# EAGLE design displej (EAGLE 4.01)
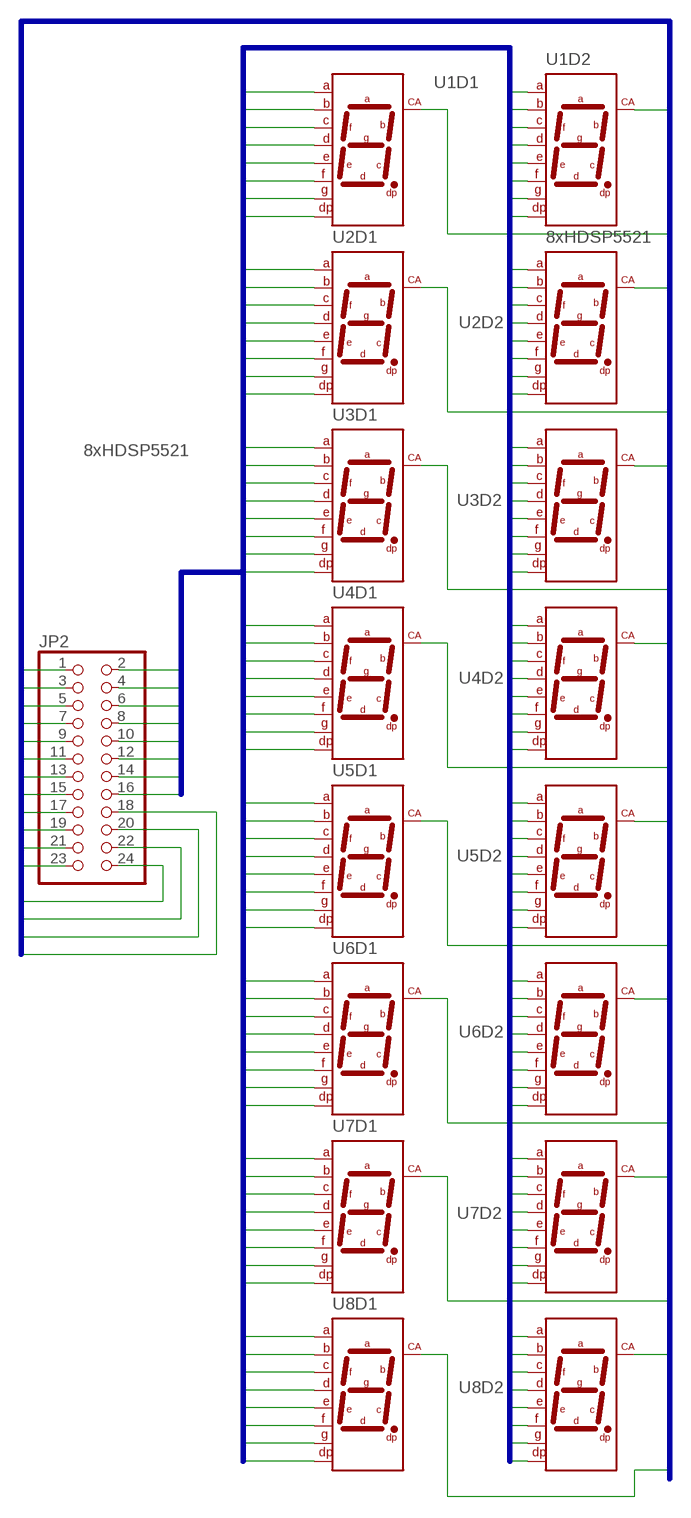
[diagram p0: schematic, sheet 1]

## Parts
JP2  PINHD-2X12  [2X12]
U1  8xHDSP5521  HD-A542D  [7SEGHD18]
U2  HD-A542D  [7SEGHD18]
U3  HD-A542D  [7SEGHD18]
U4  HD-A542D  [7SEGHD18]
U5  HD-A542D  [7SEGHD18]
U6  HD-A542D  [7SEGHD18]
U7  HD-A542D  [7SEGHD18]
U8  HD-A542D  [7SEGHD18]

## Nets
SEGMENT_KATODY_0: JP2.16 U1.11(D2:A) U1.16(D1:A) U2.11(D2:A) U2.16(D1:A) U3.11(D2:A) U3.16(D1:A) U4.11(D2:A) U4.16(D1:A) U5.11(D2:A) U5.16(D1:A) U6.11(D2:A) U6.16(D1:A) U7.11(D2:A) U7.16(D1:A) U8.11(D2:A) U8.16(D1:A)
SEGMENT_KATODY_1: JP2.14 U1.10(D2:B) U1.15(D1:B) U2.10(D2:B) U2.15(D1:B) U3.10(D2:B) U3.15(D1:B) U4.10(D2:B) U4.15(D1:B) U5.10(D2:B) U5.15(D1:B) U6.10(D2:B) U6.15(D1:B) U7.10(D2:B) U7.15(D1:B) U8.10(D2:B) U8.15(D1:B)
SEGMENT_KATODY_2: JP2.12 U1.3(D1:C) U1.8(D2:C) U2.3(D1:C) U2.8(D2:C) U3.3(D1:C) U3.8(D2:C) U4.3(D1:C) U4.8(D2:C) U5.3(D1:C) U5.8(D2:C) U6.3(D1:C) U6.8(D2:C) U7.3(D1:C) U7.8(D2:C) U8.3(D1:C) U8.8(D2:C)
SEGMENT_KATODY_3: JP2.10 U1.2(D1:D) U1.6(D2:D) U2.2(D1:D) U2.6(D2:D) U3.2(D1:D) U3.6(D2:D) U4.2(D1:D) U4.6(D2:D) U5.2(D1:D) U5.6(D2:D) U6.2(D1:D) U6.6(D2:D) U7.2(D1:D) U7.6(D2:D) U8.2(D1:D) U8.6(D2:D)
SEGMENT_KATODY_4: JP2.8 U1.1(D1:E) U1.5(D2:E) U2.1(D1:E) U2.5(D2:E) U3.1(D1:E) U3.5(D2:E) U4.1(D1:E) U4.5(D2:E) U5.1(D1:E) U5.5(D2:E) U6.1(D1:E) U6.5(D2:E) U7.1(D1:E) U7.5(D2:E) U8.1(D1:E) U8.5(D2:E)
SEGMENT_KATODY_5: JP2.6 U1.12(D2:F) U1.18(D1:F) U2.12(D2:F) U2.18(D1:F) U3.12(D2:F) U3.18(D1:F) U4.12(D2:F) U4.18(D1:F) U5.12(D2:F) U5.18(D1:F) U6.12(D2:F) U6.18(D1:F) U7.12(D2:F) U7.18(D1:F) U8.12(D2:F) U8.18(D1:F)
SEGMENT_KATODY_6: JP2.4 U1.7(D2:G) U1.17(D1:G) U2.7(D2:G) U2.17(D1:G) U3.7(D2:G) U3.17(D1:G) U4.7(D2:G) U4.17(D1:G) U5.7(D2:G) U5.17(D1:G) U6.7(D2:G) U6.17(D1:G) U7.7(D2:G) U7.17(D1:G) U8.7(D2:G) U8.17(D1:G)
SEGMENT_KATODY_7: JP2.2 U1.4(D1:DP) U1.9(D2:DP) U2.4(D1:DP) U2.9(D2:DP) U3.4(D1:DP) U3.9(D2:DP) U4.4(D1:DP) U4.9(D2:DP) U5.4(D1:DP) U5.9(D2:DP) U6.4(D1:DP) U6.9(D2:DP) U7.4(D1:DP) U7.9(D2:DP) U8.4(D1:DP) U8.9(D2:DP)
VSTUP_ANODY0: JP2.17 U1.14(D1:CA)
VSTUP_ANODY1: JP2.19 U1.13(D2:CA)
VSTUP_ANODY2: JP2.21 U2.14(D1:CA)
VSTUP_ANODY3: JP2.23 U2.13(D2:CA)
VSTUP_ANODY4: JP2.24 U3.14(D1:CA)
VSTUP_ANODY5: JP2.22 U3.13(D2:CA)
VSTUP_ANODY6: JP2.20 U4.14(D1:CA)
VSTUP_ANODY7: JP2.18 U4.13(D2:CA)
VSTUP_ANODY8: JP2.15 U5.14(D1:CA)
VSTUP_ANODY9: JP2.13 U5.13(D2:CA)
VSTUP_ANODY10: JP2.11 U6.14(D1:CA)
VSTUP_ANODY11: JP2.9 U6.13(D2:CA)
VSTUP_ANODY12: JP2.7 U7.14(D1:CA)
VSTUP_ANODY13: JP2.5 U7.13(D2:CA)
VSTUP_ANODY14: JP2.3 U8.14(D1:CA)
VSTUP_ANODY15: JP2.1 U8.13(D2:CA)

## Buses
SEGMENT_KATODY_[0..7]
VSTUP_ANODY[0..15]

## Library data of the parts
JP2 = pinhead:PINHD-2X12: PIN HEADER
U1-U8 = GM99:HD-A542D

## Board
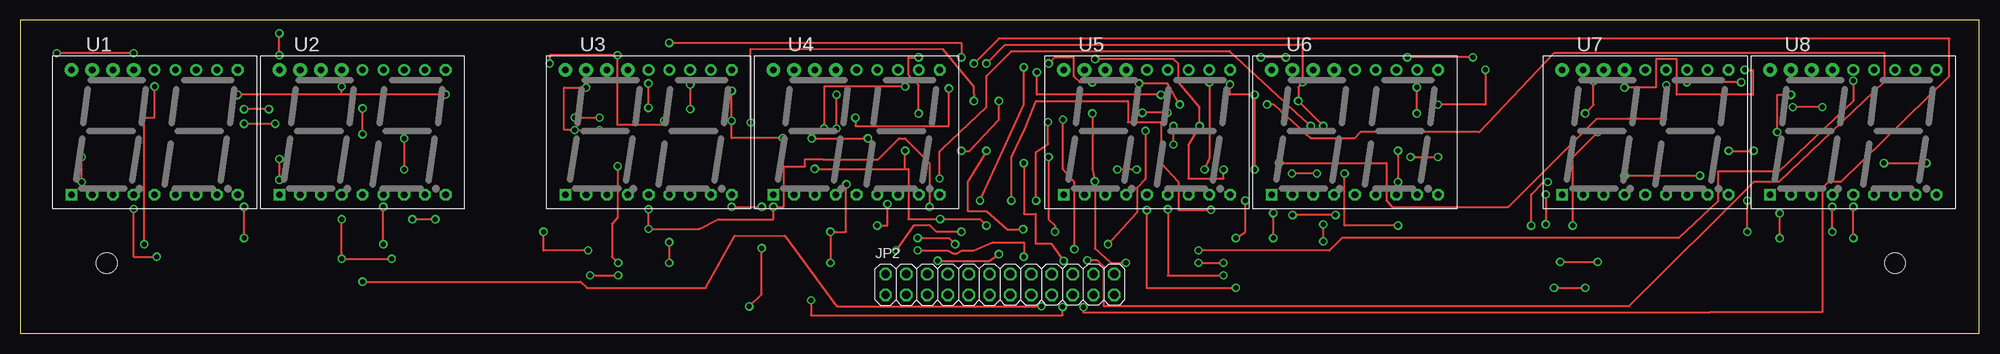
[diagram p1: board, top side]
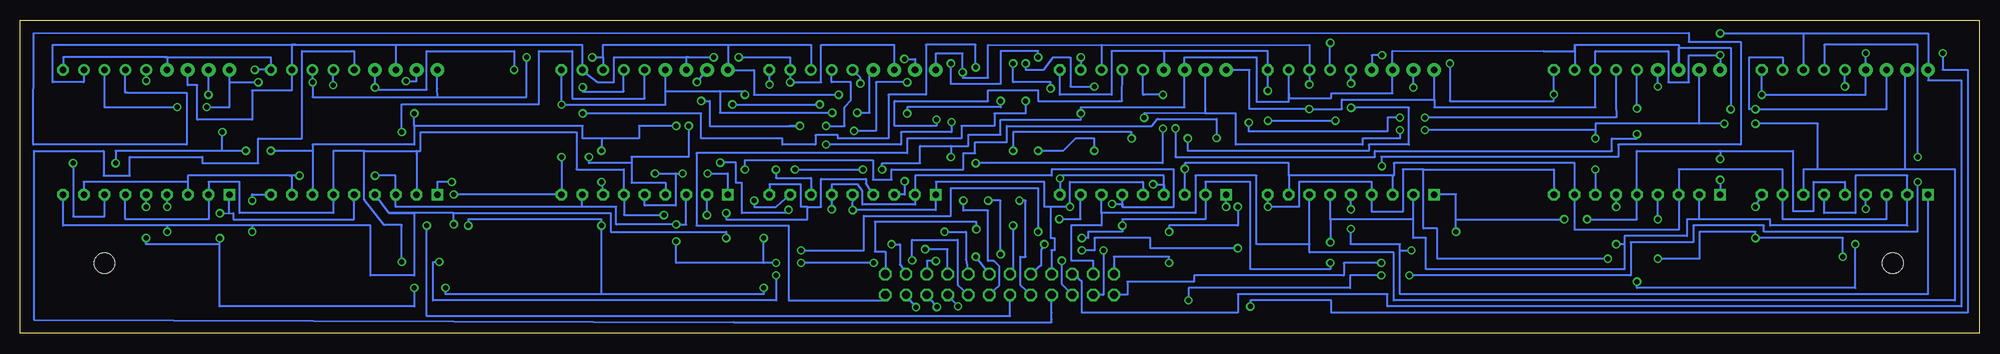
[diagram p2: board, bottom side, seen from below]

Size 239.24 x 38.27 mm. Coordinates in mm from the lower left corner, seen from the top.
Outline: 0,0 239.24,0 239.24,38.27 0,38.27 0,0
Copper layers used: Top, Bottom
Holes 2.54 mm at 10.54,8.61 228.98,8.61

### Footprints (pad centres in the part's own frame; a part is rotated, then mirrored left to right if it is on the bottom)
2X12 = drill 1.016 octagon: 1 -13.97,-1.27; 2 -13.97,1.27; 3 -11.43,-1.27; 4 -11.43,1.27; 5 -8.89,-1.27; 6 -8.89,1.27; 7 -6.35,-1.27; 8 -6.35,1.27; 9 -3.81,-1.27; 10 -3.81,1.27; 11 -1.27,-1.27; 12 -1.27,1.27; 13 1.27,-1.27; 14 1.27,1.27; 15 3.81,-1.27; 16 3.81,1.27; 17 6.35,-1.27; 18 6.35,1.27; 19 8.89,-1.27; 20 8.89,1.27; 21 11.43,-1.27; 22 11.43,1.27; 23 13.97,-1.27; 24 13.97,1.27
7SEGHD18 = drill 0.813 pad 1.422 square: 1 0,0 | drill 0.813 pad 1.422 octagon: 2 2.54,0; 3 5.08,0; 4 7.62,0; 5 10.16,0; 6 12.7,0; 7 15.24,0; 8 17.78,0; 9 20.32,0; 10 20.32,15.24 | drill 0.813 pad 1.422 round: 11 17.78,15.24; 12 15.24,15.24; 13 12.7,15.24; 14 10.16,15.24 | drill 0.813 pad 1.676 round: 15 7.62,15.24; 16 5.08,15.24; 17 2.54,15.24; 18 0,15.24

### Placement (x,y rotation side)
JP2  119.64,5.98 0 top
U1  6.22,16.97 0 top
U2  31.62,16.97 0 top
U3  66.56,16.97 0 top
U4  91.96,16.97 0 top
U5  127.44,16.97 0 top
U6  152.84,16.97 0 top
U7  188.32,16.97 0 top
U8  213.72,16.97 0 top

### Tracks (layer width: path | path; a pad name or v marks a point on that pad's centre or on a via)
SEGMENT_KATODY_0  (via drill 0.61)
  Top 0.254: v154.55,33.76 v151.51,33.76 | v126.36,12.42 126.36,13.19 125.6,13.95 v125.6,21.57 | v144.65,20.04 145.21,21.42 v145.21,30.71 | v136.34,20.04 v133.98,20.04 | v109.72,26.9 109.72,30.33 108.48,31.58 108.48,33.73 109.72,33.73 v109.72,33.76 | v30.35,27.41 30.35,27.43 | v30.35,27.41 | v27.3,27.41 v30.35,27.41
  Bottom 0.254: 145.21,32.24 v145.21,30.71 141.45,30.71 141.45,35.28 132.53,35.28 132.53,34.22 U5.16 | 157.6,33.76 v154.55,33.76 | v151.51,33.76 145.21,33.76 145.21,32.24 | 145.21,32.24 U5.11 | 193.42,35.28 193.42,33 U7.16 | 205.61,35.28 193.42,35.28 | 205.61,35.28 235.33,35.28 235.33,30.71 231.52,30.71 231.52,32.24 U8.11 | 218.79,30.33 217.65,30.33 217.65,26.14 210.94,26.14 210.94,29.7 206.1,29.7 U7.11 206.1,35.28 205.61,35.28 | U1.11 24,33.76 28.06,33.76 28.06,27.41 v27.3,27.41 11.3,27.41 U1.16 | 49.4,35.28 36.7,35.28 U2.16 36.7,34.94 30.35,34.94 v30.35,27.41 | 49.4,35.28 U2.11 | 84.32,29.37 84.32,32.24 U3.11 | 84.32,29.37 84.32,29.36 84.32,28.79 79.12,28.79 79.12,29.36 71.65,29.37 U3.16 71.65,33.02 71.65,34.55 53.21,34.52 49.4,34.52 49.4,35.28 | v126.36,12.42 123.77,12.42 123.77,8.99 JP2.16 | 125.6,22.94 v125.6,21.57 | 125.6,22.94 123.46,22.94 123.46,24.31 119.5,24.31 119.5,26.14 109.72,26.14 v109.72,26.9 109.72,27.66 97.04,27.66 U4.16 97.05,33.77 96.64,33.76 88.26,33.76 88.26,28.32 84.32,28.32 84.32,29.37 | v144.65,20.04 v136.34,20.04 | v133.98,20.04 133.98,20.81 129.33,20.81 129.33,22.94 125.6,22.94 | v109.72,33.76 U4.11 | U6.16 157.92,33.76 157.6,33.76 | 157.6,33.76 166.75,33.76 166.75,30.71 168.73,30.71 U6.11 170.62,35.28 193.42,35.28 | 218.79,30.33 218.8,30.33 | U8.16 218.8,30.33 218.79,30.33 | v30.35,27.41
SEGMENT_KATODY_1  (via drill 0.61)
  Top 0.254: v140.08,26.98 v137.03,26.98 | 211.63,32.21 211.63,29.19 202.31,29.19 202.31,33.51 199.77,33.51 199.77,30.08 v195.93,30.08 | v64.64,33 64.64,34.01 v72.92,34.01 72.92,25.48 78.61,25.48 v78.61,26.01 | v86.89,29.68 v86.87,26 86.86,23.88 v93.14,23.88 | v122.55,9.38 122.55,11.15 118.74,11.15 116.45,10.14 114.93,10.14 114.42,9.81 113.91,9.81 113.28,10.14 v109.6,10.14 | v90.55,10.42 90.55,4.8 v89.02,3.28 | v13.84,34.27 v4.44,34.27 | v150.74,20.04 v150.74,29.19 147.75,29.19 v147.75,30.43 | v178.94,32.24 178.94,27.97 v173.15,27.97 | 39.24,29.21 v26.54,29.19 | v51.94,29.21 39.24,29.21 | 39.24,29.21 v39.24,30.18 | v210.61,32.24 210.61,32.21 211.63,32.21 | 211.63,32.21 211.63,32.24
  Bottom 0.254: 221.61,33.76 208.66,33.76 208.66,32.24 U7.10 208.64,32.24 v210.61,32.24 | v150.74,29.19 150.74,29.64 153.79,29.64 | v137.03,26.98 135.5,26.98 135.5,31.47 U5.15 | v140.08,26.98 153.79,26.98 153.79,29.64 | v178.94,32.24 178.94,34.52 189.61,34.52 189.61,29.82 195.93,29.82 v195.93,30.08 U7.15 | 99.69,34.52 86.88,34.52 86.88,32.24 U3.10 v86.88,29.67 | 99.69,34.52 99.58,34.52 U4.15 | 99.69,34.52 105.96,34.52 105.96,29.19 112.26,29.19 112.26,32.24 U4.10 | 51.94,32.24 U2.10 v51.94,29.21 51.94,28.43 64.64,28.43 v64.64,33 | v72.92,34.01 74.17,34.01 U3.15 | v86.87,26 86.74,26.01 v78.61,26.01 | v109.6,10.14 108.07,10.14 108.07,11.66 101.24,11.66 101.24,10.42 v90.55,10.42 | v89.02,3.28 89.02,4.04 79.12,4.04 79.12,2.52 1.39,2.52 1.39,32.24 4.44,32.24 v4.44,34.27 | 26.54,32.24 U1.10 v26.54,29.19 13.84,29.19 U1.15 v13.84,34.27 | v150.74,20.04 150.74,21.19 135.12,21.19 135.12,18.8 132.84,18.8 132.84,20.04 124.07,20.04 124.07,22.02 122.63,22.02 122.63,23.4 118.74,23.4 118.74,25.38 101.04,25.38 100.32,26.22 93.14,26.22 v93.14,23.88 | v86.88,29.67 v86.89,29.67 v86.89,29.68 | v86.88,29.67 86.86,29.67 | v122.55,9.38 JP2.14 | U5.10 147.76,30.44 v147.75,30.43 | U6.15 160.46,29.64 160.45,29.64 | 160.45,29.64 153.79,29.64 | 160.45,29.64 160.45,27.97 v173.15,27.97 173.15,32.21 U6.10 | U8.10 234.04,33.76 221.61,33.76 | U8.15 221.34,33.76 221.61,33.76 | v39.24,30.18 U2.15
SEGMENT_KATODY_2  (via drill 0.61)
  Top 0.254: v135.02,8.61 133.22,8.61 131.24,10.37 v131.24,18.6 130.93,20.04 v130.93,26.9 | v143.89,8.61 v146.93,8.61 | v159.13,11.26 v159.13,13.31 | v149.6,16.23 149.6,12.42 v148.46,11.66 | v195.93,19.28 v205.15,19.28 | v117.98,13.19 117.22,13.97 v112.34,13.97 108.45,13.97 108.46,20.12 108.07,20.12 | v119.5,28.43 119.5,26.14 115.95,22.33 v114.93,22.33 | 108.07,20.12 v108.07,22.33 | v97.02,20.12 108.07,20.12 | 108.07,20.12 108.05,20.12 | 108.07,20.12
  Bottom 0.254: 206.37,19.28 218.79,19.28 218.79,18.52 | 218.79,18.52 231.52,18.52 231.52,17 U8.8 | v135.02,8.61 v143.89,8.61 | 148.46,8.61 159.13,8.61 v159.13,11.26 | v146.93,8.61 148.46,8.61 | v149.6,16.23 149.6,15.47 146.93,15.47 U5.8 | 148.46,8.61 v148.46,11.66 | 159.18,13.31 166.47,13.31 166.47,15.47 170.58,15.47 | 193.42,17 193.42,15.47 170.58,15.47 | v195.93,19.28 193.42,19.28 193.42,17 | 193.42,17 U7.3 | 24,17 24,13.95 11.3,13.95 U1.3 11.3,17 | 24,17 24,20.04 36.7,20.04 36.7,17 | 24,17 U1.8 | v117.98,13.19 117.98,7.85 JP2.12 | 84.32,19.28 84.32,17 U3.8 | 71.65,19.28 U3.3 | 71.65,19.28 71.5,19.28 71.5,20.81 49.4,20.81 U2.8 49.4,12.68 36.7,12.68 36.7,17 | 71.65,19.28 84.32,19.28 | 84.32,19.28 84.32,20.81 97.02,20.81 v97.02,20.12 97.03,19.58 U4.3 | 36.7,17 U2.3 | v130.93,26.9 130.93,27.66 119.5,27.66 v119.5,28.43 | v114.93,22.33 111.88,22.33 110.36,23.85 108.07,23.85 v108.07,22.33 | U5.3 131.24,16.97 v131.24,18.6 | v159.13,13.31 159.18,13.31 | U6.3 157.92,13.31 159.18,13.31 | U6.8 170.62,15.47 170.58,15.47 | v205.15,19.28 206.37,19.28 | U7.8 206.1,19.28 206.37,19.28 | U8.3 218.8,18.52 218.79,18.52 | U4.8 109.74,13.97 v112.34,13.97
SEGMENT_KATODY_3  (via drill 0.61)
  Top 0.254: v160.65,14.46 v155.39,14.46 | v44.32,10.9 v44.32,15.47 | v114.17,10.9 113.41,11.66 v109.6,11.66 | v79.24,11.15 v79.24,8.61 | v188.08,8.74 v192.65,8.74 | v105.89,15.83 105.89,13.19 v104.64,13.19 | v140.14,15.17 140.14,7.09 v146.93,7.09
  Bottom 0.254: 201.04,17 201.04,14.71 212.47,14.71 212.47,18.52 216.28,18.52 216.28,17 | 201.04,17 U7.6 | 216.28,17 216.28,13.95 226.42,13.95 U8.6 | 216.28,17 U8.2 | v155.39,14.46 155.39,17 U6.2 | v160.65,14.46 160.65,14.51 165.53,14.51 165.53,16.97 U6.6 165.54,20.04 171.32,20.04 171.32,24.62 190.37,24.62 190.37,22.33 190.86,22.33 | 197.23,22.33 190.86,22.33 | 197.23,22.33 201.04,22.33 201.04,17 | 8.76,17 8.76,13.19 25.52,13.19 25.52,13.95 34.16,13.95 | 34.16,13.95 U2.2 34.16,17 | 8.76,17 8.76,19.28 15.11,19.28 15.11,14.71 18.92,14.71 U1.6 18.92,17 | 8.76,17 U1.2 | v44.32,15.47 U2.6 44.32,17 | 43.3,10.9 v44.32,10.9 | 43.3,10.9 43.3,11.92 35.68,11.92 35.68,13.95 34.16,13.95 | 79.24,13.95 79.24,17 U3.6 | 79.24,13.95 70.15,13.95 69.14,13.95 69.11,13.94 | 94.51,17 94.51,13.95 104.64,13.95 v104.64,13.19 104.64,12.42 108.83,12.42 108.83,11.66 v109.6,11.66 | 104.64,15.47 98.34,15.47 98.34,20.04 113.28,20.04 113.28,19.28 129.97,19.28 129.97,17 U5.2 129.98,16.92 | v114.17,10.9 114.57,10.24 114.57,8.31 JP2.10 | 79.24,13.95 v79.24,11.15 | v79.24,8.61 79.24,7.85 89.02,7.85 89.02,18.52 94.51,18.52 94.51,17 | 94.51,17 U4.2 | 43.3,10.9 43.3,7.85 67.56,7.85 67.56,11.66 69.1,11.65 69.11,11.65 69.11,13.94 | 197.23,22.33 197.23,16.39 194.79,13.26 192.65,13.26 v192.65,8.74 | v188.08,8.74 188.84,8.74 188.84,4.04 146.93,4.04 v146.93,7.09 | 69.1,14.69 69.11,14.68 | 69.1,14.69 69.1,13.94 69.11,13.94 | U3.2 69.1,14.69 | v140.14,15.17 U5.6 140.14,18.21 136.95,18.21 136.39,17.4 136.39,15.75 129.97,15.75 129.97,16.92 129.98,16.92 | 129.98,16.92 129.99,16.92 | U7.2 190.86,21.97 190.86,22.33 | 104.64,15.47 104.66,15.47
  Bottom 0.254: 104.66,15.47 U4.6 | 104.66,15.47 104.67,15.47 | 104.64,15.47 104.64,15.83 v105.89,15.83
SEGMENT_KATODY_4  (via drill 0.61)
  Top 0.254: v223.9,11.66 v223.9,15.47 | v214.88,11.64 v214.88,14.68 | v158.36,19.56 v155.32,19.56 | v186.56,18.52 186.05,18.52 184.53,17 v184.53,13.19 | v187.32,5.57 v191.13,5.57 | v50.67,13.95 v47.87,13.95 | v111.04,15.47 111.04,20.81 108.07,23.85 107.33,23.85 104.77,21.29 98.01,21.29 98.01,21.31 95.85,21.31 95.85,20.43 93.26,20.43 93.26,15.47 v91.97,15.47 91.97,13.95 85.21,13.95 82.95,12.78 v76.73,12.78 v76.73,15.17 | v63.88,12.42 63.88,10.14 v69.34,10.14 | v31.62,21.31 v31.62,18.77 | v137.59,15.07 137.56,14.62 137.56,5.57 v148.46,5.57 | v168.27,13.19 161.74,13.19 v161.74,19.56
  Bottom 0.254: v223.9,15.47 223.9,17 U8.5 | v223.9,11.66 223.9,10.9 214.9,10.9 | 214.9,10.9 v214.88,11.64 | v148.46,5.57 148.46,4.8 168.27,4.8 | 168.27,4.8 v168.27,13.19 168.27,13.95 184.53,13.95 v184.53,13.19 | v161.74,19.56 159.2,19.56 | 214.9,10.9 214.9,3.28 191.13,3.28 v191.13,5.57 | v187.32,5.57 187.32,4.8 168.27,4.8 | 31.62,22.33 41.78,22.33 U2.5 41.78,13.95 v47.87,13.95 | 31.62,22.33 22.73,22.33 22.73,14.96 20.19,14.96 20.19,18.52 16.38,18.52 U1.5 | 31.62,22.33 v31.62,21.31 | 63.88,13.95 63.88,17 66.54,17 U3.1 | 63.88,13.95 v50.67,13.95 | 113.41,15.47 v111.04,15.47 111.04,18.52 102.13,18.52 102.13,17 U4.5 | 113.41,15.47 113.41,11.66 112.92,11.66 112.92,10.16 113.3,10.16 JP2.8 | 127.43,18.52 127.43,17 U5.1 | 127.43,18.52 114.17,18.52 114.17,15.47 113.41,15.47 | 70.73,10.14 70.73,10.9 76.73,10.9 v76.73,12.78 | 70.73,10.14 70.73,4.8 6.22,4.8 U1.1 6.22,17 | v91.97,15.47 91.97,17 U4.1 | v63.88,12.42 63.88,13.95 | 70.73,10.14 v69.34,10.14 | 127.43,18.52 127.45,15.07 v137.59,15.07 137.56,17 U5.5 | v31.62,18.77 U2.1 | U3.5 v76.72,15.17 v76.73,15.17 | U6.1 152.84,19.56 v155.32,19.56 | U6.5 163,15.62 159.2,15.62 159.2,19.56 | 159.2,19.56 v158.36,19.56 | U7.1 188.32,18.52 v186.56,18.52 | U7.5 198.48,13.95 213.23,13.95 213.23,14.71 v214.88,14.68 213.72,14.71 U8.1
SEGMENT_KATODY_5  (via drill 0.61)
  Top 0.254: v220.09,27.66 v216.48,27.66 | v210.18,30.71 v203.55,30.71 | v177.41,33.76 v169.39,33.76 | v31.62,34.01 v31.62,36.68 | v81.81,30.43 v81.81,27.43 | v139.29,29.19 124.15,29.19 v124.15,31.93
  Bottom 0.254: 152.83,35.28 142.67,35.28 142.67,32.24 U5.12 | 168.08,33.76 168.08,35.28 152.83,35.28 | 188.31,28.91 203.55,28.91 v203.55,30.71 203.55,31.55 U7.12 | v169.39,33.76 168.08,33.76 | v177.41,33.76 177.41,28.91 188.31,28.91 | 66.54,28.6 77.82,28.6 77.82,27.43 v81.81,27.43 89.1,27.43 89.1,32.21 U4.18 | 66.54,28.6 U3.18 | 107.18,35.26 81.81,35.28 81.81,32.24 U3.12 v81.81,30.43 | 107.18,35.26 107.18,32.21 U4.12 | 107.18,35.26 121.03,35.28 121.03,31.25 124.15,31.25 v124.15,31.93 124.15,34.22 127.44,34.22 U5.18 | 21.46,36.68 6.22,36.68 U1.18 6.22,30.97 2.15,30.97 2.15,3.28 72.26,3.28 72.26,4.8 90.55,4.8 90.55,2.52 109.6,2.52 109.6,6.33 110.74,7.27 JP2.6 | 21.46,36.68 U1.12 | v31.62,36.68 21.46,36.68 | 66.54,28.6 66.54,27.66 46.86,27.66 U2.12 46.86,34.52 37.97,34.52 37.97,30.71 35.43,30.71 35.43,34.01 v31.62,34.01 U2.18 | v139.29,29.19 149.65,29.19 149.65,32.21 U6.18 152.83,35.28 | 168.09,33.76 | 168.08,33.76 168.09,33.76 | U6.12 168.08,33.76 168.09,33.76 | U7.18 188.32,29.95 188.31,28.91 | U8.12 228.96,27.66 v220.09,27.66 | v216.48,27.66 213.71,27.66 U8.18 213.72,30.71 v210.18,30.71
SEGMENT_KATODY_6  (via drill 0.61)
  Top 0.254: v131.26,33.56 140.86,33.56 141.45,33 141.45,30.71 144.04,27.66 v144.04,25.38 142.67,23.09 142.67,18.95 146.96,18.95 v146.96,20.02 | v168.27,22.33 v168.27,18.52 | v208.66,22.33 v211.7,22.33 | v159.13,25.38 v156.08,28.43 156.08,30.13 v156.61,30.74 156.61,35.28 120.26,35.28 v117.98,33 | v216.28,29.19 214.57,29.19 v214.57,24.62 | v46.86,23.85 v46.86,20.04 | v70.73,24.87 v67.69,24.87 66.42,24.87 66.42,30.08 v69.1,30.08 | v27.3,25.63 v31.11,25.63 | v113.41,29.95 113.41,25.38 101.98,25.38 | v101.98,26.37 101.98,25.38 | 101.98,25.38 101.98,25.35 | v191.13,26.9 192.15,27.92 v192.15,30.84 | v227.63,20.81 v232.81,20.81
  Bottom 0.254: 168.29,23.85 170.56,23.85 170.56,25.38 191.13,25.38 | 191.13,25.38 v191.13,26.9 | 191.13,25.38 191.13,23.09 203.55,23.09 | v227.63,20.81 227.63,22.33 214.57,22.33 | v211.7,22.33 214.57,22.33 | v159.13,25.38 163.7,25.38 163.7,23.85 168.29,23.85 | v216.28,29.19 216.28,32.24 U8.17 | 214.57,22.33 v214.57,24.62 | 145.33,25.38 v144.04,25.38 155.04,25.38 155.04,28.43 v156.08,28.43 | 46.86,24.87 v46.86,23.85 | 34.16,25.63 46.86,25.63 46.86,24.87 | v46.86,20.04 U2.7 | 34.16,25.63 U2.17 | 90.77,26.9 90.77,23.09 75.31,23.09 75.31,23.85 70.73,23.85 v70.73,24.87 | 46.86,24.87 v67.69,24.87 | U4.17 94.49,27.43 94.49,26.9 90.77,26.9 | 107.21,14.71 107.21,13.19 110.89,13.19 110.89,8.92 108.22,8.92 108.22,7.25 JP2.4 | 107.21,14.71 107.21,17 U4.7 | 9.01,20.04 9.01,31.47 U1.17 | 19.68,20.04 21.46,20.04 U1.7 | 9.01,20.04 19.68,20.04 | 81.78,10.9 81.78,9.88 71.5,9.88 71.5,4.04 2.92,4.04 2.92,20.04 9.01,20.04 | 81.78,10.9 81.78,17 U3.7 | 107.21,14.71 95.73,14.71 95.73,19.28 88.26,19.28 88.26,10.9 81.78,10.9 | v31.11,25.63 34.16,25.63 | v27.3,25.63 19.68,25.63 19.68,20.04 | v117.98,33 117.98,30.71 113.41,30.71 v113.41,29.95 | 90.77,26.9 102,26.93 101.98,26.93 v101.98,26.37 | v69.1,30.08 v69.11,30.08 U3.17 | v131.26,33.56 129.97,33.56 129.98,33.53 U5.17 | U5.7 142.68,19 146.96,19 v146.96,20.02 | v156.61,30.74 U6.17 | 168.29,23.85 168.27,23.85 v168.27,22.33 | v168.27,18.52 168.27,18.54 U6.7 | U7.17 190.86,30.84 v192.15,30.84 | U7.7 203.56,23.09 203.55,23.09 | v208.66,22.33 203.55,22.33 203.55,23.09 | U8.7 228.96,14.33 232.81,14.33 v232.81,20.81
SEGMENT_KATODY_7  (via drill 0.61)
  Top 0.254: v169.79,21.57 v173.16,21.57 | v153.03,11.66 v153.03,14.71 | v210.94,12.42 v210.94,16.23 | v221.31,12.42 v221.31,15.47 | v186.3,17 v186.3,13.34 | v13.84,15.22 13.84,9.38 v16.63,9.38 | v27.3,11.66 v27.3,15.47 | v98.93,8.61 v98.93,12.42 99.58,12.43 100.86,12.43 100.86,18.23 v100.88,18.23 | v157.6,25.38 155.9,26.88 147.7,34.52 121.03,34.52 117.98,31.47 117.98,27.66 112.64,22.58 112.28,22.24 112.28,19.23 | v86.86,15.47 v90.55,15.47 | 112.28,19.23 112.26,19.23 v112.26,18.95 | 112.28,19.23 112.29,19.23 | v45.33,9.12 v39.24,9.12 v39.24,13.95
  Bottom 0.254: 164.61,20.81 164.61,18.44 160.46,18.44 U6.4 | 164.61,20.81 169.79,20.81 v169.79,21.57 | 210.94,13.19 196.46,13.19 196.46,7.09 191.13,7.09 191.13,14.71 194.18,14.71 | 210.94,13.19 221.31,13.19 | 143.12,15.47 141.45,15.47 141.45,18.9 135.96,18.9 135.96,18.29 135.5,17.61 U5.4 | 143.12,15.47 143.12,13.95 153.03,13.95 v153.03,14.71 | v153.03,11.66 153.03,12.42 167.13,12.42 167.13,14.71 186.3,14.71 | 186.3,14.71 194.18,14.71 | 210.94,13.19 v210.94,12.42 | U7.9 208.66,17 210.94,17 v210.94,16.23 | 221.31,13.19 v221.31,12.42 | v186.3,17 185.82,16.97 U6.9 173.16,17 | v186.3,13.34 186.3,14.71 | v13.84,15.22 U1.4 13.84,17 | v16.63,9.38 16.63,11.66 v27.3,11.66 27.3,12.42 34.16,12.42 34.16,9.12 v39.24,9.12 | v27.3,15.47 U1.9 26.54,17 | v39.24,13.95 U2.4 39.24,17 | U4.9 112.26,17 v112.26,18.95 112.26,19.28 99.56,19.28 99.56,19.23 99.58,19.23 U4.4 99.58,18.23 v100.88,18.23 | v98.93,8.61 98.93,9.38 105.67,9.38 JP2.2 | 67.86,20.04 51.94,20.04 U2.9 | 67.86,20.04 67.86,12.8 66.16,12.8 66.16,9.12 v45.33,9.12 | U3.9 86.86,17 v86.86,15.47 83.05,15.47 83.05,18.52 74.16,18.52 U3.4 74.18,14.86 70.38,14.86 70.38,20.04 67.86,20.04 | v98.93,12.42 98.93,13.19 90.55,13.19 v90.55,15.47 | 164.61,20.81 164.61,21.57 157.6,21.57 v157.6,25.38 | U5.9 147.76,18.21 143.91,18.21 143.91,15.47 143.12,15.47 | v173.16,21.57 173.16,17 | 173.16,17 173.15,17 | 194.18,14.71 U7.4 | 221.28,15.47 v221.31,15.47 221.34,15.47 U8.4 | U8.9 234.04,13.19 221.31,13.19
VSTUP_ANODY0  (via drill 0.61)
  Top 0.254: v41.78,6.33 68.45,6.33 69.21,5.57 83.69,5.57 87.24,11.94 93.31,11.97 99.69,3.28 v124.71,3.31 | v16.38,30.2 16.38,26.39 15.11,26.39 v15.11,10.9
  Bottom 0.254: v15.11,10.9 15.11,5.57 41.78,5.57 v41.78,6.33 | 16.38,30.18 v16.38,30.2 U1.14 | v124.71,3.31 JP2.17
VSTUP_ANODY1  (via drill 0.61)
  Top 0.254: v7.49,18.52 v7.49,21.57 | v69.59,7.09 v73.02,7.09 | v96.57,4.04 96.54,2.24 127.3,2.24 v127.3,3.23
  Bottom 0.254: v7.49,21.57 7.49,35.28 18.92,35.28 U1.13 | v7.49,18.52 7.49,12.42 26.28,12.42 26.28,13.19 34.92,13.19 34.92,11.15 42.54,11.15 42.54,7.09 v69.59,7.09 | v73.02,7.09 76.83,7.09 76.83,5.57 96.57,5.57 v96.57,4.04 | v127.3,3.23 JP2.19
VSTUP_ANODY2  (via drill 0.61)
  Top 0.254: v98.17,25.07 98.17,30.18 v108.07,30.18 | v116.45,33 119.5,36.05 235.63,36.05 235.63,31.47 222.37,18.52 220.85,18.52 220.09,17.76 220.09,2.59 206.37,2.59 206.37,2.52 129.84,2.52 v129.84,3.2 | v41.78,24.36 v41.78,27.51
  Bottom 0.254: v41.78,24.36 41.78,23.85 44.83,23.85 44.83,22.33 73.78,22.33 73.78,21.57 98.17,21.57 v98.17,25.07 | v108.07,30.18 110.99,30.18 110.99,33.76 113.08,33.76 114.24,32.24 116.45,32.24 v116.45,33 | v129.84,3.2 JP2.21 | v41.78,27.51 U2.14
VSTUP_ANODY3  (via drill 0.61)
  Top 0.254: v67.69,26.39 v70.73,26.39 | v89.2,25.78 89.2,32.14 89.19,34.79 112.64,34.78 116.43,30.15 v116.45,28.43
  Bottom 0.254: 44.32,27.33 44.32,26.39 v67.69,26.39 | v70.73,26.39 72.26,26.39 72.26,24.69 89.2,24.69 v89.2,25.78 | v116.45,28.43 116.45,26.9 120.26,26.9 120.26,25.38 124.3,25.38 124.3,23.85 130.93,23.85 130.93,22.02 156.66,22.02 156.66,13.19 145.41,13.19 145.41,4.04 133.98,4.04 JP2.23 | 44.32,27.33 44.32,27.36 | 44.32,27.33 U2.13
VSTUP_ANODY4  (via drill 0.61)
  Top 0.254: v122.47,12.73 120.54,12.73 117.98,14.96 115.69,14.96 115.69,18.52 v117.98,22.33 | v96.64,23.85 v103.5,23.85 | v76.7,27.59 v76.7,30.56
  Bottom 0.254: v122.47,12.73 122.47,13.64 134.87,13.64 134.87,10.01 133.6,10.01 133.6,7.85 JP2.24 | v117.98,22.33 117.98,24.62 103.5,24.62 v103.5,23.85 | v96.64,23.85 96.64,22.33 74.54,22.33 74.54,23.09 69.62,23.09 69.62,27.59 v76.7,27.59 | U3.14 76.7,32.21 v76.7,30.56
VSTUP_ANODY5  (via drill 0.61)
  Top 0.254: v132.84,10.9 136.37,14.76 136.37,17.81 137.41,18.9 v137.41,24.77 | v130.93,30.71 129.41,30.71 128.65,31.47 128.65,33.76 126.36,33.76 v125.6,33 | v114.93,33.76 114.93,35.54 v79.24,35.54
  Bottom 0.254: v132.84,10.9 131.82,10.9 131.82,8.41 JP2.22 | v137.41,24.77 134.74,24.77 134.74,30.71 v130.93,30.71 | v125.6,33 125.6,30.48 119.5,30.48 119.5,34.52 114.93,34.52 v114.93,33.76 | v79.24,35.54 79.27,35.28 U3.13
VSTUP_ANODY6  (via drill 0.61)
  Top 0.254: v99.69,25.05 v99.69,29.19 | v122.55,20.81 122.55,14.63 124,14.63 124,10.98 125.9,10.98 v127.43,8.84
  Bottom 0.254: v99.69,29.19 101.98,29.19 102.12,29.19 U4.14 | v99.69,25.05 99.69,20.81 v122.55,20.81 | JP2.20 128.53,8.84 v127.43,8.84
VSTUP_ANODY7  (via drill 0.61)
  Top 0.254: v128.72,10.29 128.72,18.52 127.35,20.04 v127.35,26.14
  Bottom 0.254: v128.72,10.29 125.98,10.29 125.98,7.85 JP2.18 | v127.35,26.14 127.35,25.38 132.46,25.38 132.46,28.43 121.03,28.43 121.03,29.72 114.93,29.72 114.93,28.43 105.02,28.43 104.66,28.42 U4.13
VSTUP_ANODY8  (via drill 0.61)
  Top 0.254: v152.27,27.99 153.11,27.99 157.6,23.85 162.94,23.85 163.7,24.62 178.18,24.62 187.32,34.27 227.71,34.27 227.71,30.86 214.75,18.52 211.7,18.52 196.46,3.28 132.38,3.28 132.38,8.16 131.54,8.92 v130.32,8.92 | v141.6,27.99 140.13,30.56 v136.65,30.56
  Bottom 0.254: v152.27,27.99 v141.6,27.99 | v130.32,8.92 130.32,11.43 124.76,11.43 124.76,5.95 JP2.15 | U5.14 136.65,31.26 v136.65,30.56
VSTUP_ANODY9  (via drill 0.61)
  Top 0.254: v140.84,23.09 v140.84,25.38 | v125.52,25.84 125.52,23.17 124.07,22.18 v124.07,16.23
  Bottom 0.254: v140.84,25.38 138.55,25.38 138.55,27.66 137.79,28.5 137.79,30.71 140.15,30.71 140.15,32.24 U5.13 | v140.84,23.09 131.69,23.09 131.69,24.62 125.52,24.62 v125.52,25.84 | JP2.13 119.65,5.87 119.65,8.18 120.34,8.84 121.03,8.84 121.03,15.01 124.07,15.01 v124.07,16.23
VSTUP_ANODY10  (via drill 0.61)
  Top 0.254: v189.61,13.19 189.61,21.57 v192.65,24.62
  Bottom 0.254: v189.61,13.19 189.61,2.11 118.35,2.11 JP2.11 | v192.65,24.62 192.65,28.02 175.89,28.02 175.89,34.52 171.85,34.52 171.85,28.73 163,28.73 U6.14
VSTUP_ANODY11  (via drill 0.61)
  Top 0.254: v122.55,32.54 122.55,28.04 v117.22,16.23 | v170.56,26.9 v170.56,30.1
  Bottom 0.254: v117.22,16.23 116.45,16.23 116.45,9.38 117.09,9.38 117.09,5.9 JP2.9 | v122.55,32.54 122.55,35.28 128.65,35.28 128.65,29.19 133.22,29.19 133.22,23.85 139.39,23.85 139.39,24.23 142.13,24.23 142.13,23.09 146.17,23.09 146.17,23.85 156.08,23.85 156.08,26.9 v170.56,26.9 | v170.56,30.1 170.56,29.57 165.54,29.57 U6.13
VSTUP_ANODY12
  Bottom 0.254: 198.78,34.52 204.85,34.52 204.85,23.85 210.18,23.85 210.18,20.81 217.04,20.81 217.04,21.57 225.88,21.57 225.88,19.28 229.08,19.28 229.08,22.33 237.61,22.33 237.61,1.68 152.14,1.38 113.28,1.38 113.28,1.68 113.29,2.52 JP2.7 | 198.78,34.52 198.75,34.52 | U7.14 198.48,34.52 198.78,34.52
VSTUP_ANODY13  (via drill 0.61)
  Top 0.254: v112.03,8.89 118.31,8.89 v119.5,9.68 | v121.03,16.23 121.03,21.57 122.7,25.07 124.07,28.43 135.28,28.43 135.28,25.84 139.31,25.84 139.31,20.81 141.45,18.52 141.45,15.12 v145.41,15.12 | v153.77,20.88 153.77,20.86 166.82,20.86 166.82,16.23 167.51,15.47 181.73,15.47 192.53,26.27 201.01,26.27 201.01,30.36 v201.04,30.36
  Bottom 0.254: v119.5,9.68 119.5,16.23 v121.03,16.23 | v145.41,15.12 145.41,14.71 151.1,14.71 151.1,18.42 151.84,18.42 151.84,20.88 v153.77,20.88 | 112.03,8.92 v112.03,8.89 112.03,6 JP2.5 | U7.13 201.02,30.36 v201.04,30.36
VSTUP_ANODY14  (via drill 0.61)
  Top 0.254: v106.95,10.14 109.09,13.19 111.12,13.19 111.88,12.42 v114.93,12.42 | v143.89,10.14 159.89,10.14 161.41,11.66 202.56,11.66 207.36,16.16 207.36,19.81 214.75,19.81 223.87,28.43 v223.87,30.89
  Bottom 0.254: v114.93,12.42 114.93,17.76 125.6,17.76 125.6,14.38 136.22,14.38 136.22,10.14 v143.89,10.14 | JP2.3 106.95,4.71 v106.95,10.14 106.95,10.16 | U8.14 v223.88,30.89 v223.87,30.89
VSTUP_ANODY15  (via drill 0.61)
  Top 0.254: v72.94,20.45 72.94,14.18 72.26,13.41 72.26,9.38 v73.02,8.61
  Bottom 0.254: v72.94,20.45 73.02,21.57 44.06,21.57 44.06,23.09 29.13,23.09 29.13,35.66 35.47,35.66 35.47,36.74 237.64,36.7 237.66,23.09 218.94,23.09 218.94,29.42 226.18,29.42 226.18,29.44 | v73.02,8.61 77.59,8.61 77.59,7.09 95.88,7.09 95.88,6.33 104.03,6.33 104.03,4.73 JP2.1 | 226.18,29.44 226.13,29.44 | U8.13 226.42,29.44 226.18,29.44

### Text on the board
Top: Strana soucastek
Bottom: Strana spoju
